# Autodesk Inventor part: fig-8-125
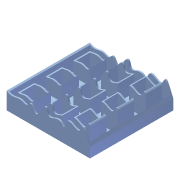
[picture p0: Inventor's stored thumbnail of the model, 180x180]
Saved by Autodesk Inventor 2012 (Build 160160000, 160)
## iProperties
Shininess: 64.0
Length Units: 11269
Angle Units: 11279
Time Units: 11290
Mass Units: 11283
Length Display Precision: 3
Angle Display Precision: 2
Compacted: True
Part Number: fig-8-125
Document SubType Name: Modeling
Created: 2002-12
Designer: deepak
Density: 1 g/cm^3
Material: Default
Density: 0.0
Volumn: 0.0
Area: 0.0
PropertySet Name: Model Information
Control State: 0
Master: False
Checked Out: False
Author: deepak
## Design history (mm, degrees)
sketch "Sketch1"
  geometry: L1 (-32.188, 30.089)-(27.812, 30.089); L2 (27.812, 30.089)-(27.812, -29.911); L3 (27.812, -29.911)-(-32.188, -29.911); L4 (-32.188, -29.911)-(-32.188, 30.089)
  constraints: 8 end point, 2 parallel, 1 horizontal, 1 perpendicular
  dimensions: "d0" = 60 distance of L1.start L1.end; "d1" = 60 distance of L3.end L1.start
extrude "Extrusion1" new body sketch "Sketch1" stored distance "d2" = 20; taper "d3" = 0 deg
sketch "Sketch5"
  geometry: L1 (-27.812, 30.089)-(32.188, 30.089) reference; L2 (-27.812, -29.911)-(-27.812, 30.089) reference; L3 (-22.812, 25.089)-(-12.812, 25.089); L4 (-12.812, 25.089)-(-12.812, 15.089); L5 (-12.812, 15.089)-(-22.812, 15.089); L6 (-22.812, 15.089)-(-22.812, 25.089)
  constraints: 8 end point, 2 parallel, 1 horizontal, 1 perpendicular
  dimensions: "d8" = 10 distance of L3.start L3.end; "d9" = 10 distance of L5.end L3.start; "d10" = 5 distance between parallel lines of L2 L6; "d11" = 5 distance between parallel lines of L1 L3
extrude "Extrusion2" cut sketch "Sketch5" distance "d12" = 50; taper "d13" = 0 deg
pattern_linear "Rectangular Pattern1" dims "d16" = 20
shell "Shell2" dims "d21" = 1
sketch "Sketch2"
  geometry: 17 further points
  constraints: 17 other
extrude_surface "ExtrusionSrf1" sketch "Sketch2" dims "d4" = 70, "d5" = 0
split "Split2"
body "Solid1"
body "Srf1"
